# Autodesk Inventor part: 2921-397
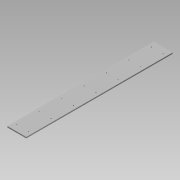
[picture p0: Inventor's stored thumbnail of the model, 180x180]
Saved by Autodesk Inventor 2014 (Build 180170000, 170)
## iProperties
Company: NHTSA
Created: 2012-08
Part Number: 2921-397
Material: Steel
Document SubType Name: Modeling
Designer: Mike Vanvoorhis
Density: 7.85 g/cm^3
Mass: 3979.19 g
Surface Area: 1720.51 cm^2
Volume: 506.903 cm^3
Project: CHILD SIDE IMPACT SLED
Description: ANTI-REBOUND SLIDER BASE
Appearance: Steel
Stock Number: PL 6.4 (1/4") x 101.6 (4") x 787.4 (31")
Author: Dave Walker
Title: Anti_Rebound_Slider_Base
Subject: Child Side Impact Sled
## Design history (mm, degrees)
sketch "Sketch1"
  geometry: L1 (-50.8, 0)-(50.8, 0); L2 (50.8, 0)-(50.8, 6.35); L3 (50.8, 6.35)-(-50.8, 6.35); L4 (-50.8, 6.35)-(-50.8, 0); 2 further points
  constraints: 8 end point, 2 parallel, 1 coincident, 1 horizontal, 1 midpoint, 1 perpendicular
  dimensions: "d0" = 101.6 distance of L3.end L2.end; "d1" = 6.35 distance of L2.end L1.end
extrude "Extrusion1" new body sketch "Sketch1" distance "d2" = 787.4; taper "d3" = 0 deg
sketch "Sketch2"
  geometry: L1 (101.6, 0)-(0, 0) reference; L2 (101.6, 0)-(82.55, 0); L3 (82.55, 0)-(82.55, 31.75); L4 (82.55, 31.75)-(82.55, 152.4); L5 (82.55, 152.4)-(82.55, 273.05); L6 (82.55, 273.05)-(82.55, 393.7); L7 (82.55, 393.7)-(82.55, 514.35); L8 (82.55, 514.35)-(82.55, 635); L9 (82.55, 635)-(82.55, 755.65); L10 (82.55, 31.75)-(19.05, 31.75); L11 (19.05, 31.75)-(19.05, 152.4); L12 (19.05, 152.4)-(19.05, 273.05); L13 (19.05, 273.05)-(19.05, 393.7); L14 (19.05, 393.7)-(19.05, 514.35); L15 (19.05, 514.35)-(19.05, 635); L16 (19.05, 635)-(19.05, 755.65)
  constraints: 30 end point, 8 perpendicular, 5 collinear, 1 point on line
  dimensions: "d4" = 19.05 distance of L1.start L2.end; "d5" = 31.75 distance of L2.end L3.end; "d6" = 120.65 distance of L3.end L4.end; "d7" = 120.65 distance of L4.end L5.end; "d8" = 120.65 distance of L5.end L6.end; "d9" = 120.65 distance of L6.end L7.end; "d10" = 120.65 distance of L7.end L8.end; "d11" = 120.65 distance of L8.end L9.end; "d12" = 63.5 distance of L3.end L10.end; "d13" = 120.65 distance of L10.end L11.end; "d14" = 120.65 distance of L11.end L12.end; "d15" = 120.65 distance of L12.end L13.end; "d16" = 120.65 distance of L13.end L14.end; "d17" = 120.65 distance of L14.end L15.end; "d18" = 120.65 distance of L15.end L16.end
hole "Hole1" sketch "Sketch2" at (19.05, 755.65), (19.05, 635), (19.05, 514.35), (19.05, 393.7), (19.05, 273.05), (19.05, 152.4), (19.05, 31.75), (82.55, 31.75), (82.55, 152.4), (82.55, 273.05), (82.55, 393.7), (82.55, 635)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 diameter "d19" = 3.9624; stored, may be unused: countersink angle "d23" = 82 deg, drill point angle "d25" = 118 deg; dims "d20" = 19.05, "d21" = 9.525, "d22" = 6.35, "d24" = 25.4
body "Solid1"
